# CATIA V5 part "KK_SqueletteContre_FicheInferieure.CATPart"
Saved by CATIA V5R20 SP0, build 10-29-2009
Part number: Squelette_contre_fiche_inferieure
Bounding box of the stored display mesh (mm): x -938.001 to 160, y 640 to 1041.992, z -1600 to -967.22
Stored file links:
  G:\Khaled_CFAO_2011\ST2M\ST2M_GR2\aboulegue\Khaled\CAD_thinkMOTION\KK_SqueletteContre_FicheInferieure.CATPart
  G:\Khaled_CFAO_2011\ST2M\ST2M_GR2\aboulegue\Khaled\CAD_thinkMOTION\KK_Train_Atterrissage.CATProduct
  G:\Khaled_CFAO_2011\ST2M\ST2M_GR2\aboulegue\CFAO_aboulegue\CFAO_aboulegue_fichiers_catia\Squelette contre friche.CATPart
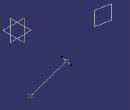
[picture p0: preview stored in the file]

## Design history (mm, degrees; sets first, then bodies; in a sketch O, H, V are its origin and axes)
Set1
  Point1 "Point.15": linked copy from another document
  Point2: linked copy from another document
  Plane1 "Plan reference contre fiche superieue": linked copy from another document
Set2 "Set squelette contre fiche inferieure"
  Line1: type PtPt, FirstPoint Point1, SecondPoint Point2
  Line2: type Normal, RefPoint Point1, RefSkin Plane1, Start -200, End 200
Body1 (main body)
